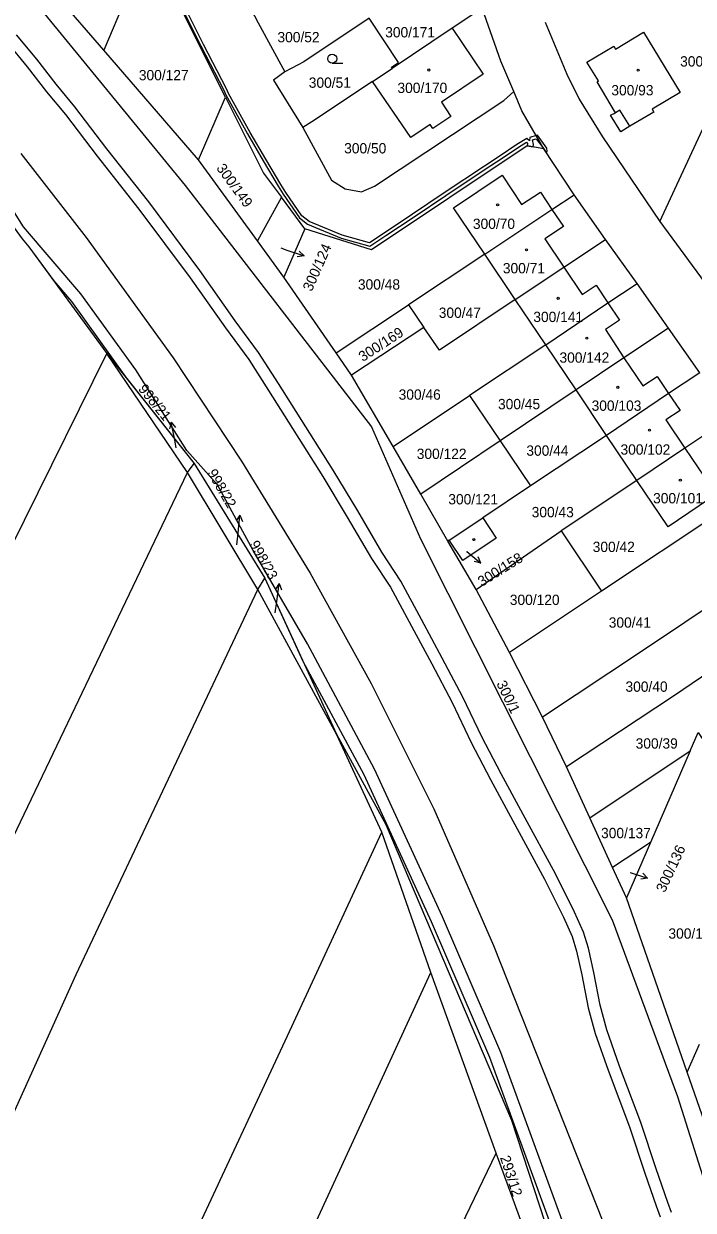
# Model space of a CAD drawing. Extents: x -757266 to -753360, y -1162585 to -1157740.
# Drawn here: x -754815.2 to -754704.7, y -1160778.7 to -1160582.8 of the extents above; entities that cross this region are included whole.
import ezdxf

# ---------------------------------------------------------------- set-up
doc = ezdxf.new("R2010")
doc.units = 0
for name, color, linetype in [('Hranice parcel', 7, 'Continuous'), ('Parcelní čísla', 7, 'Continuous'), ('Pop  PČ popisy', 7, 'Continuous'), ('Poz předměty', 7, 'Continuous'), ('Vnitřní kresba', 7, 'Continuous'), ('Věcná břemena k části', 7, 'Continuous'), ('Značky budov', 7, 'Continuous'), ('Značky kultur', 7, 'Continuous')]:
    doc.layers.add(name, color=color, linetype=linetype)

msp = doc.modelspace()

# ---------------------------------------------------------------- linework, layer by layer
at = {"layer": 'Hranice parcel'}
for p, q in [((-754794.56, -1160569.62), (-754801.98, -1160587.2)), ((-754781.89, -1160594.97), (-754794.56, -1160569.62)), ((-754801.98, -1160587.2), (-754810.26, -1160577.6)), ((-754744.49, -1160583.58), (-754754.41, -1160590.2)), ((-754710.21, -1160615.49), (-754696.01, -1160584.78)), ((-754786.38, -1160605.28), (-754801.98, -1160587.2)), ((-754757.66, -1160592.36), (-754754.41, -1160590.2)), ((-754786.38, -1160605.28), (-754781.89, -1160594.97)), ((-754724.38, -1160611.08), (-754729.39, -1160603.49)), ((-754776.64, -1160618.67), (-754786.38, -1160605.28)), ((-754772.69, -1160611.48), (-754776.64, -1160618.67)), ((-754768.82, -1160616.69), (-754772.69, -1160611.48)), ((-754728.03, -1160613.49), (-754724.38, -1160611.08)), ((-754719.16, -1160618.44), (-754724.38, -1160611.08)), ((-754739.11, -1160620.88), (-754728.03, -1160613.49)), ((-754710.21, -1160615.49), (-754700.75, -1160628.37)), ((-754768.82, -1160616.69), (-754772.27, -1160624.68)), ((-754772.27, -1160624.68), (-754776.64, -1160618.67)), ((-754713.98, -1160625.74), (-754719.16, -1160618.44)), ((-754739.11, -1160620.88), (-754751.7, -1160629.26)), ((-754734.09, -1160628.36), (-754739.11, -1160620.88)), ((-754763.63, -1160637.18), (-754772.27, -1160624.68)), ((-754708.8, -1160633.07), (-754713.98, -1160625.74)), ((-754763.63, -1160637.18), (-754751.7, -1160629.26)), ((-754751.7, -1160629.26), (-754749.16, -1160633)), ((-754729.06, -1160635.82), (-754734.09, -1160628.36)), ((-754749.16, -1160633), (-754761.1, -1160640.84)), ((-754703.64, -1160640.46), (-754708.8, -1160633.07)), ((-754801.47, -1160637.28), (-754787.07, -1160655.41)), ((-754788.15, -1160656.91), (-754801.47, -1160637.28)), ((-754761.1, -1160640.84), (-754763.63, -1160637.18)), ((-754729.06, -1160635.82), (-754741.62, -1160644.22)), ((-754724.04, -1160643.25), (-754729.06, -1160635.82)), ((-754754.21, -1160652.64), (-754761.1, -1160640.84)), ((-754754.21, -1160652.64), (-754741.62, -1160644.22)), ((-754741.62, -1160644.22), (-754736.58, -1160651.67)), ((-754724.04, -1160643.25), (-754736.58, -1160651.67)), ((-754719.04, -1160650.79), (-754724.04, -1160643.25)), ((-754698.75, -1160647.97), (-754706.07, -1160652.91)), ((-754719.04, -1160650.79), (-754731.54, -1160659.12)), ((-754714, -1160658.26), (-754719.04, -1160650.79)), ((-754749.66, -1160660.51), (-754754.21, -1160652.64)), ((-754736.58, -1160651.67), (-754749.66, -1160660.51)), ((-754736.58, -1160651.67), (-754731.54, -1160659.12)), ((-754706.07, -1160652.91), (-754714, -1160658.26)), ((-754788.15, -1160656.91), (-754787.07, -1160655.41)), ((-754787.07, -1160655.41), (-754775.41, -1160674.38)), ((-754776.56, -1160676.24), (-754788.15, -1160656.91)), ((-754714, -1160658.26), (-754726.49, -1160666.57)), ((-754692.34, -1160658.16), (-754719.83, -1160676.48)), ((-754745.19, -1160668.25), (-754749.66, -1160660.51)), ((-754731.54, -1160659.12), (-754739.46, -1160664.42)), ((-754744.98, -1160668.11), (-754739.46, -1160664.42)), ((-754740.56, -1160676.24), (-754726.49, -1160666.57)), ((-754726.49, -1160666.57), (-754719.83, -1160676.48)), ((-754744.98, -1160668.11), (-754745.19, -1160668.25)), ((-754740.56, -1160676.24), (-754745.19, -1160668.25)), ((-754776.56, -1160676.24), (-754775.41, -1160674.38)), ((-754775.41, -1160674.38), (-754763.57, -1160700.1)), ((-754763.57, -1160700.1), (-754776.56, -1160676.24)), ((-754735.04, -1160686.62), (-754740.56, -1160676.24)), ((-754719.83, -1160676.48), (-754735.04, -1160686.62)), ((-754729.57, -1160697.33), (-754735.04, -1160686.62)), ((-754725.63, -1160705.48), (-754729.57, -1160697.33)), ((-754756.13, -1160716.27), (-754763.57, -1160700.1)), ((-754721.76, -1160713.94), (-754705.2, -1160702.85)), ((-754705.2, -1160702.85), (-754711.77, -1160717.97)), ((-754721.76, -1160713.94), (-754725.63, -1160705.48)), ((-754718.02, -1160722.13), (-754721.76, -1160713.94)), ((-754748.01, -1160739.46), (-754756.13, -1160716.27)), ((-754711.77, -1160717.97), (-754718.02, -1160722.13)), ((-754711.77, -1160717.97), (-754715.74, -1160727.11)), ((-754715.74, -1160727.11), (-754718.02, -1160722.13)), ((-754705.7, -1160755.9), (-754715.74, -1160727.11)), ((-754737.22, -1160769.26), (-754748.01, -1160739.46)), ((-754705.7, -1160755.9), (-754703.67, -1160751.28)), ((-754699.8, -1160772.96), (-754705.7, -1160755.9)), ((-754727.18, -1160796.65), (-754737.22, -1160769.26))]:
    msp.add_line(p, q, dxfattribs=at)
for points in [[(-754832.33, -1160557.56), (-754811.8, -1160581.2), (-754788.57, -1160609.52), (-754757.81, -1160649.38), (-754749.73, -1160667.84), (-754718.09, -1160730.78), (-754707.28, -1160759.93), (-754701.46, -1160778.37), (-754686.64, -1160826.48), (-754676.87, -1160861.18), (-754663.2, -1160911.68), (-754637.02, -1161012.69), (-754632.76, -1161025.61)], [(-754778.27, -1160579.33), (-754776.51, -1160582.67), (-754772.11, -1160590.8)], [(-754739.52, -1160580.26), (-754743.24, -1160582.74), (-754744.49, -1160583.58)], [(-754734.33, -1160594.03), (-754736.45, -1160589.03), (-754739.52, -1160580.26)], [(-754758.21, -1160581.94), (-754768.98, -1160589.13), (-754772.11, -1160590.8)], [(-754754.41, -1160590.2), (-754754.53, -1160590.01), (-754753.35, -1160589.23), (-754758.21, -1160581.94)], [(-754744.49, -1160583.58), (-754739.38, -1160591.15), (-754746.26, -1160595.8), (-754744.71, -1160598.13), (-754747.66, -1160600.11), (-754748.12, -1160599.47), (-754751.3, -1160601.62), (-754757.66, -1160592.36)], [(-754729.14, -1160582.6), (-754725.55, -1160591.14), (-754723.55, -1160595.26), (-754719.68, -1160601.5), (-754710.21, -1160615.49)], [(-754715.16, -1160599.76), (-754716.65, -1160600.7), (-754718.35, -1160597.91), (-754717.54, -1160597.57), (-754720.58, -1160592.41), (-754720.37, -1160592.28), (-754722.26, -1160589.19), (-754717.81, -1160586.52), (-754717.52, -1160587.01), (-754712.9, -1160584.23), (-754706.87, -1160594.18), (-754711.5, -1160596.96), (-754711.22, -1160597.44), (-754715.16, -1160599.76)], [(-754772.11, -1160590.8), (-754773.97, -1160592.17), (-754769.14, -1160599.99)], [(-754757.66, -1160592.36), (-754767.66, -1160599.04), (-754769.14, -1160599.99)], [(-754769.14, -1160599.99), (-754764.39, -1160608.66), (-754762.14, -1160610.09), (-754759.46, -1160610.61), (-754757.3, -1160609.63), (-754735.94, -1160595.52), (-754734.33, -1160594.03)], [(-754729.39, -1160603.49), (-754732.98, -1160597.23), (-754734.33, -1160594.03)], [(-754781.89, -1160594.97), (-754775.64, -1160607.48), (-754772.69, -1160611.48)], [(-754729.39, -1160603.49), (-754732.09, -1160603.01), (-754757.82, -1160620.18), (-754768.82, -1160616.69)], [(-754739.11, -1160620.88), (-754744.26, -1160613.2), (-754736.25, -1160607.84), (-754733.03, -1160612.69), (-754729.94, -1160610.64), (-754728.03, -1160613.49)], [(-754815.45, -1160618.35), (-754814.35, -1160619.65), (-754801.47, -1160637.28)], [(-754734.09, -1160628.36), (-754726.08, -1160623.02), (-754719.16, -1160618.44)], [(-754729.06, -1160635.82), (-754718.8, -1160628.9), (-754713.98, -1160625.74)], [(-754734.09, -1160628.36), (-754746.61, -1160636.74), (-754749.16, -1160633)], [(-754708.8, -1160633.07), (-754716.15, -1160637.97), (-754724.04, -1160643.25)], [(-754891.98, -1160831.42), (-754868.12, -1160781.77), (-754828.74, -1160692.31), (-754801.47, -1160637.28)], [(-754703.64, -1160640.46), (-754708.78, -1160643.87), (-754719.04, -1160650.79)], [(-754706.07, -1160652.91), (-754702.94, -1160657.54), (-754700.61, -1160655.97), (-754698.62, -1160658.97), (-754708.86, -1160665.87), (-754714, -1160658.26)], [(-754896.59, -1160890.79), (-754881.3, -1160860.74), (-754865.2, -1160824.84), (-754823.57, -1160730.83), (-754788.15, -1160656.91)], [(-754739.46, -1160664.42), (-754737.22, -1160667.73), (-754742.76, -1160671.44), (-754744.98, -1160668.11)], [(-754886.7, -1160919.35), (-754871.74, -1160884.3), (-754806.57, -1160739.78), (-754776.56, -1160676.24)], [(-754699.08, -1160677), (-754713.07, -1160686.37), (-754729.57, -1160697.33)], [(-754694.1, -1160684.44), (-754707.98, -1160693.81), (-754725.63, -1160705.48)], [(-754705.2, -1160702.85), (-754703.89, -1160699.83), (-754702.89, -1160701.3)], [(-754763.57, -1160700.1), (-754755.44, -1160715.04), (-754734.69, -1160763.81), (-754712.71, -1160831.19)], [(-754857.86, -1160938.84), (-754824.9, -1160863.88), (-754771.7, -1160749.92), (-754756.13, -1160716.27)], [(-754843.82, -1160948.33), (-754793.71, -1160838.79), (-754748.01, -1160739.46)], [(-754827.41, -1160959.42), (-754797.79, -1160894.25), (-754775.86, -1160849.5), (-754737.22, -1160769.26)]]:
    msp.add_lwpolyline(points, dxfattribs=at)
at = {"layer": 'Pop  PČ popisy'}
for p, q in [((-754772.75, -1160619.85), (-754771.78, -1160620.19)), ((-754771.78, -1160620.19), (-754768.943, -1160621.167)), ((-754768.943, -1160621.167), (-754770.052, -1160621.314)), ((-754768.943, -1160621.167), (-754769.726, -1160620.368)), ((-754790.863, -1160648.614), (-754791.163, -1160649.693)), ((-754790.29, -1160651.56), (-754790.863, -1160648.614)), ((-754790.863, -1160648.614), (-754790.18, -1160649.502)), ((-754790.03, -1160652.86), (-754790.29, -1160651.56)), ((-754779.516, -1160663.965), (-754780.119, -1160664.909)), ((-754779.83, -1160666.95), (-754779.516, -1160663.965)), ((-754779.516, -1160663.965), (-754779.123, -1160665.014)), ((-754780.05, -1160668.88), (-754779.83, -1160666.95)), ((-754742.08, -1160669.92), (-754742.05, -1160669.95)), ((-754742.05, -1160669.95), (-754739.751, -1160671.879)), ((-754739.751, -1160671.879), (-754740.84, -1160671.619)), ((-754739.751, -1160671.879), (-754740.196, -1160670.852)), ((-754773.022, -1160675.228), (-754773.658, -1160676.15)), ((-754773.44, -1160678.2), (-754773.022, -1160675.228)), ((-754773.022, -1160675.228), (-754772.666, -1160676.29)), ((-754773.7, -1160680.09), (-754773.44, -1160678.2)), ((-754715.12, -1160722.92), (-754715.09, -1160722.93)), ((-754715.09, -1160722.93), (-754712.236, -1160723.857)), ((-754712.236, -1160723.857), (-754713.034, -1160723.072)), ((-754712.236, -1160723.857), (-754713.343, -1160724.024))]:
    msp.add_line(p, q, dxfattribs=at)
at = {"layer": 'Poz předměty'}
for p, q in [((-754815.67, -1160604.24), (-754804.89, -1160618.1)), ((-754804.89, -1160618.1), (-754790.53, -1160638.01)), ((-754790.53, -1160638.01), (-754779.26, -1160655.05)), ((-754779.26, -1160655.05), (-754767.92, -1160673.56)), ((-754767.92, -1160673.56), (-754757.89, -1160691.75)), ((-754757.89, -1160691.75), (-754747.51, -1160712.42)), ((-754747.51, -1160712.42), (-754737.69, -1160735)), ((-754737.69, -1160735), (-754727.18, -1160761.52)), ((-754727.18, -1160761.52), (-754719.63, -1160780.56))]:
    msp.add_line(p, q, dxfattribs=at)
at = {"layer": 'Vnitřní kresba'}
for p, q in [((-754716.81, -1160597.08), (-754717.54, -1160597.57)), ((-754715.16, -1160599.76), (-754716.81, -1160597.08)), ((-754728.03, -1160613.49), (-754726.12, -1160616.32)), ((-754726.12, -1160616.32), (-754729.19, -1160618.37)), ((-754729.19, -1160618.37), (-754726.08, -1160623.02)), ((-754726.08, -1160623.02), (-754723.06, -1160627.55)), ((-754723.06, -1160627.55), (-754720.74, -1160625.99)), ((-754720.74, -1160625.99), (-754718.8, -1160628.9)), ((-754718.8, -1160628.9), (-754716.89, -1160631.76)), ((-754716.89, -1160631.76), (-754719.21, -1160633.31)), ((-754719.21, -1160633.31), (-754716.15, -1160637.97)), ((-754716.15, -1160637.97), (-754713.01, -1160642.62)), ((-754713.01, -1160642.62), (-754710.68, -1160641.05)), ((-754710.68, -1160641.05), (-754708.78, -1160643.87)), ((-754708.78, -1160643.87), (-754706.88, -1160646.67)), ((-754706.88, -1160646.67), (-754709.21, -1160648.24)), ((-754709.21, -1160648.24), (-754706.07, -1160652.91))]:
    msp.add_line(p, q, dxfattribs=at)
at = {"layer": 'Věcná břemena k části'}
for points in [[(-754789.09, -1160580.22), (-754785.97, -1160586.47), (-754782.19, -1160593.8), (-754781.83, -1160594.55), (-754778.25, -1160601.03), (-754775.7, -1160605.47), (-754773.22, -1160609.64), (-754772.39, -1160610.95), (-754769.67, -1160614.89), (-754768.38, -1160615.92), (-754762.79, -1160618.21), (-754758.06, -1160619.53), (-754755.44, -1160617.81), (-754750.78, -1160614.71), (-754745.55, -1160611.17), (-754738.9, -1160606.75), (-754736.43, -1160605.15), (-754733.56, -1160603.19), (-754732.24, -1160602.4)], [(-754729.09, -1160603.94), (-754728.82, -1160603.91), (-754728.89, -1160603.36), (-754730.43, -1160601.25), (-754730.64, -1160601.31), (-754731.65, -1160601.6), (-754731.74, -1160602.19), (-754732.18, -1160601.78), (-754733.82, -1160602.77), (-754736.71, -1160604.73), (-754739.18, -1160606.33), (-754745.83, -1160610.75), (-754751.06, -1160614.29), (-754755.72, -1160617.39), (-754758.14, -1160618.99), (-754762.63, -1160617.73), (-754768.12, -1160615.48), (-754769.31, -1160614.55), (-754771.97, -1160610.67), (-754772.8, -1160609.38), (-754775.26, -1160605.21), (-754777.81, -1160600.79), (-754781.39, -1160594.33), (-754781.75, -1160593.58), (-754785.53, -1160586.25), (-754788.65, -1160580)], [(-754817.9, -1160586.01), (-754814.63, -1160589.94), (-754811.43, -1160594.06), (-754808.33, -1160597.8), (-754803.07, -1160604.72), (-754796.2, -1160613.44), (-754787.75, -1160624.77), (-754781.91, -1160633.04), (-754778.08, -1160638.27), (-754774.8, -1160643.38), (-754765.83, -1160657.56), (-754761.8, -1160664.27), (-754757.79, -1160671.13), (-754754.7, -1160675.86), (-754751.21, -1160682.3), (-754747.87, -1160688.52), (-754744.52, -1160694.89), (-754741.35, -1160701.46), (-754738.15, -1160707.61), (-754734.5, -1160714.4), (-754729.23, -1160724.06), (-754726.14, -1160730.34), (-754724.7, -1160733.49), (-754723.96, -1160735.93), (-754723.1, -1160739.82), (-754722.04, -1160745.3), (-754720.89, -1160749.53), (-754718.75, -1160755.57), (-754715.23, -1160764.91), (-754712.69, -1160772.59), (-754710.82, -1160777.97), (-754710.18, -1160779.79)], [(-754708.31, -1160779.09), (-754708.89, -1160777.41), (-754710.83, -1160771.84), (-754713.35, -1160764.23), (-754716.85, -1160754.91), (-754718.98, -1160748.93), (-754720.09, -1160744.84), (-754721.13, -1160739.45), (-754722.02, -1160735.44), (-754722.82, -1160732.77), (-754724.33, -1160729.47), (-754727.45, -1160723.15), (-754732.79, -1160713.36), (-754736.38, -1160706.68), (-754739.58, -1160700.53), (-754742.74, -1160693.99), (-754746.12, -1160687.55), (-754749.54, -1160681.18), (-754752.97, -1160674.86), (-754756.08, -1160670.08), (-754760.07, -1160663.26), (-754764.12, -1160656.54), (-754773.15, -1160642.23), (-754776.44, -1160637.13), (-754780.3, -1160631.86), (-754786.14, -1160623.58), (-754794.58, -1160612.26), (-754801.49, -1160603.5), (-754806.76, -1160596.55), (-754809.88, -1160592.8), (-754813.06, -1160588.7), (-754816.4, -1160584.69)], [(-754783.25, -1160658.97), (-754788.31, -1160653.27), (-754796.68, -1160639.96), (-754805.76, -1160627.42), (-754815.25, -1160616.36), (-754818.74, -1160610.74), (-754823.42, -1160605.21), (-754828.34, -1160600.47), (-754823.86, -1160606.85), (-754815.45, -1160618.35), (-754814.35, -1160619.65), (-754810.24, -1160625.28), (-754807.34, -1160628.66), (-754798.41, -1160641.13), (-754787.07, -1160655.41), (-754775.41, -1160674.38), (-754769.12, -1160688.05), (-754759.07, -1160706.77), (-754747.95, -1160731.05), (-754738.33, -1160753.44), (-754728.02, -1160781.63)], [(-754732.24, -1160602.4), (-754732.05, -1160602.59), (-754732.09, -1160603.01), (-754731.13, -1160603.18), (-754731.07, -1160602.78), (-754731.21, -1160602), (-754730.63, -1160601.83), (-754729.39, -1160603.49), (-754729.09, -1160603.94)], [(-754726.12, -1160781.01), (-754736.47, -1160752.68), (-754746.11, -1160730.29), (-754757.29, -1160705.87), (-754768.37, -1160685.22), (-754777.32, -1160669.81), (-754783.25, -1160658.97)]]:
    msp.add_lwpolyline(points, dxfattribs=at)
at = {"layer": 'Značky budov'}
for centre in [(-754748.3368, -1160590.4792), (-754713.8068, -1160590.4992), (-754736.9868, -1160612.7292), (-754732.2268, -1160620.1592), (-754727.0068, -1160628.1692), (-754722.2568, -1160634.7392), (-754717.1568, -1160642.8592), (-754711.9268, -1160649.9392), (-754706.8268, -1160658.1892), (-754740.9268, -1160667.9892)]:
    msp.add_circle(centre, 0.175, dxfattribs=at)
at = {"layer": 'Značky kultur'}
msp.add_line((-754764.293, -1160589.36), (-754762.543, -1160589.36), dxfattribs=at)
msp.add_circle((-754764.2929, -1160588.6098), 0.75, dxfattribs=at)

# ---------------------------------------------------------------- texts
at = {"layer": 'Parcelní čísla'}
for s, p in [('300/52', (-754773.33, -1160585.9)), ('300/171', (-754755.546, -1160585.09)), ('300/61', (-754706.87, -1160589.9)), ('300/127', (-754796.21, -1160592.17)), ('300/51', (-754768.16, -1160593.41)), ('300/170', (-754753.526, -1160594.27)), ('300/93', (-754718.22, -1160594.66)), ('300/50', (-754762.32, -1160604.24)), ('300/70', (-754741.07, -1160616.71)), ('300/71', (-754736.13, -1160624.04)), ('300/48', (-754760.05, -1160626.72)), ('300/47', (-754746.71, -1160631.39)), ('300/141', (-754731.1, -1160632.08)), ('300/142', (-754726.78, -1160638.79)), ('300/46', (-754753.33, -1160644.9)), ('300/45', (-754736.93, -1160646.47)), ('300/103', (-754721.48, -1160646.73)), ('300/122', (-754750.34, -1160654.68)), ('300/44', (-754732.25, -1160654.15)), ('300/102', (-754716.71, -1160653.97)), ('300/121', (-754745.13, -1160662.18)), ('300/101', (-754711.33, -1160662.01)), ('300/43', (-754731.37, -1160664.3)), ('300/42', (-754721.3, -1160670.04)), ('300/120', (-754734.98, -1160678.78)), ('300/41', (-754718.65, -1160682.53)), ('300/40', (-754715.89, -1160693.11)), ('300/39', (-754714.21, -1160702.49)), ('300/137', (-754719.92, -1160717.28)), ('300/118', (-754708.8, -1160733.87))]:
    msp.add_text(s, height=1.7, dxfattribs=at).set_placement(p)
for s, rotation, p in [('300/149', 306, (-754783.497, -1160606.689)), ('300/124', 66, (-754767.687, -1160627.148)), ('300/169', 33, (-754759.242, -1160638.696)), ('998/21', 309, (-754796.41, -1160643.164)), ('998/22', 300, (-754784.966, -1160656.945)), ('998/23', 298.999997, (-754778.023, -1160668.722)), ('300/158', 32, (-754739.6, -1160675.815)), ('300/1', 296, (-754737.233, -1160691.762)), ('300/136', 65, (-754709.398, -1160726.373)), ('293/12', 288, (-754736.618, -1160769.982))]:
    msp.add_text(s, height=1.7, rotation=rotation, dxfattribs=at).set_placement(p)

doc.saveas('drawing.dxf')
